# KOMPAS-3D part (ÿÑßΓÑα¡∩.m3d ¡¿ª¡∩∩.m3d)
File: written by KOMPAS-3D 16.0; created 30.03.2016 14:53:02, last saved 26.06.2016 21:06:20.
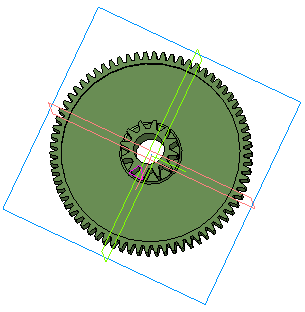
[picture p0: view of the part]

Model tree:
1. Эскиз:1
2. Операция выдавливания:1
     Расстояние 1 = 15
3. Эскиз:2
4. Вырезать элемент выдавливания:1
     Расстояние 1 = 3
5. Эскиз:3
6. Вырезать элемент выдавливания:2
     Расстояние 1 = 4
7. Эскиз:4
8. Операция выдавливания:2
     Расстояние 1 = 20
9. Эскиз:5
10. Вырезать элемент выдавливания:3
     Расстояние 1 = 104
11. Эскиз:6
12. Скругление:1
     Радиус = 0.5
13. Эскиз:7
14. Вырезать элемент выдавливания:5
     Расстояние 1 = 23
15. Массив по концентрической сетке:2  (with: Вырезать элемент выдавливания:5, Эскиз:7)  (70 pattern instances)
     Геометрический массив = 69; Шаг 2 = 360
16. Вырезать элемент выдавливания:6
     Расстояние 1 = 19
17. Массив по концентрической сетке:3  (with: Вырезать элемент выдавливания:6, Эскиз:6)  (12 pattern instances)
     Геометрический массив = 11; Шаг 2 = 360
